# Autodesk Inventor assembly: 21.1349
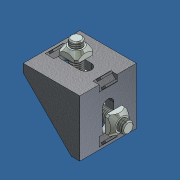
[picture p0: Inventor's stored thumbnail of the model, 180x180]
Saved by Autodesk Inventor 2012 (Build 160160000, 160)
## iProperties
Created: 2007-01
Part Number: 21.1349
Document SubType Name: Assembly
Designer: Andy Moles
Mass: 96.2012 g
Surface Area: 138.686 cm^2
Volume: 26.753 cm^3
Density: 3.5959 g/cm^3
Description: ANGLE 45 GD-Z
Author: Andy Moles
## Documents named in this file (5)
- C:\Andys Backup Data\ANDY'S INVENTOR\INVENTOR LIBRARIES\PARTS LIBRARY\FASTENING ELEMENTS\21.1349 ANGLE 45 GD-Z.iam
- C:\Andys Backup Data\ANDY'S INVENTOR\INVENTOR LIBRARIES\PARTS LIBRARY\FASTENING ELEMENTS\SUBCOMPONENTS\21.1349 ANGLE 45 GD-Z.ipt
- C:\Andys Backup Data\ANDY'S INVENTOR\INVENTOR LIBRARIES\PARTS LIBRARY\FASTENING ELEMENTS\WASHERS\21.1127 M8 ROUND WASHER.ipt
- C:\Andys Backup Data\ANDY'S INVENTOR\INVENTOR LIBRARIES\PARTS LIBRARY\FASTENING ELEMENTS\NUTS\21.1351 M8 SQUARE NUT.ipt
- C:\Andys Backup Data\ANDY'S INVENTOR\INVENTOR LIBRARIES\PARTS LIBRARY\FASTENING ELEMENTS\SCREWS CAP\21.1280 M8X22.ipt
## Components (7 placed, 4 different names)
1. 21.1349 ANGLE 45 GD-Z:1 — Flush:1, Flush:2, Mate:1, Mate:2, Mate:3, Mate:4, Mate:5, Mate:6, Mate:7, Mate:10, Mate:11
2. 21.1280 M8X22:2 — Insert:1, Mate:2, Mate:4, Mate:9
3. 21.1280 M8X22:1 — Insert:2, Mate:6, Mate:7, Mate:8
4. 21.1127 M8 ROUND WASHER — Insert:1, Mate:3
5. 21.1127 M8 ROUND WASHER:2 — Insert:2, Mate:5
6. 21.1351 M8 SQUARE NUT:1 — Mate:8, Mate:11
7. 21.1351 M8 SQUARE NUT:2 — Mate:9, Mate:10
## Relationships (15: Mate 11, Flush 2, Insert 2)
- Flush:1: 21.1349 ANGLE 45 GD-Z:1
- Flush:2: 21.1349 ANGLE 45 GD-Z:1
- Mate:1: 21.1349 ANGLE 45 GD-Z:1
- Insert:1: 21.1280 M8X22:2 ↔ 21.1127 M8 ROUND WASHER
- Insert:2: 21.1280 M8X22:1 ↔ 21.1127 M8 ROUND WASHER:2
- Mate:2: 21.1349 ANGLE 45 GD-Z:1 ↔ 21.1280 M8X22:2
- Mate:3: 21.1349 ANGLE 45 GD-Z:1 ↔ 21.1127 M8 ROUND WASHER
- Mate:4: 21.1349 ANGLE 45 GD-Z:1 ↔ 21.1280 M8X22:2
- Mate:5: 21.1349 ANGLE 45 GD-Z:1 ↔ 21.1127 M8 ROUND WASHER:2
- Mate:6: 21.1349 ANGLE 45 GD-Z:1 ↔ 21.1280 M8X22:1
- Mate:7: 21.1349 ANGLE 45 GD-Z:1 ↔ 21.1280 M8X22:1
- Mate:8: 21.1280 M8X22:1 ↔ 21.1351 M8 SQUARE NUT:1
- Mate:9: 21.1280 M8X22:2 ↔ 21.1351 M8 SQUARE NUT:2
- Mate:10: 21.1349 ANGLE 45 GD-Z:1 ↔ 21.1351 M8 SQUARE NUT:2
- Mate:11: 21.1349 ANGLE 45 GD-Z:1 ↔ 21.1351 M8 SQUARE NUT:1
